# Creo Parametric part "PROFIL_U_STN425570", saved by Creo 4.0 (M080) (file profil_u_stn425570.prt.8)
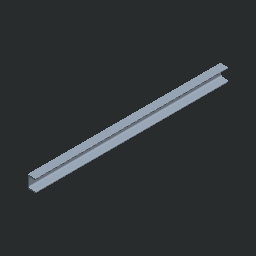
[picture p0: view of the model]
Units: millimeter Kilogram Sec (mmKs); MM, KILOGRAM, SECS
Materials in the file: OCEL_N

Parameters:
  MFG_WP_MATERIAL = "OCEL"
  NAZOV = "PROFIL_U_STN425570"
  NORMA = "STN 42 5570"
  PTC_MATERIAL_NAME = "OCEL_N"

Other parameters: HMOTNOST, HUSTOTA, D5, D1, D10

Created from: U.PRT

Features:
  1. datum plane "DTM1"
  2. datum plane "DTM2"
  3. datum plane "DTM3"

Layers: 1, 2, 3, 4, 5, 6, 7, 8, 9, 10, 11, 12, 13, 14, 15, 16, 17, 18, 19, 20, 21, 22, 23, 24, 25, 26, 27, 28, 29, 30, 31, 32

Family table entries: GENERIC, PROFIL_U_65, PROFIL_U_STN425570, value(d_val), value(i_val), PROFIL_U_80, PROFIL_U_STN425570, 2/T, 2/ , 2/-, PROFIL_U_100, PROFIL_U_STN425570, !/I, 2/Y, 2/!, 2//, PROFIL_U_120, PROFIL_U_STN425570, 2/^, 2/", 2/0, PROFIL_U_140, PROFIL_U_STN425570, !/N, 2/$, PROFIL_U_160, PROFIL_U_STN425570, 2/d, 2/%, PROFIL_U_180, PROFIL_U_STN425570, 2/ , 2/&, PROFIL_U_200, PROFIL_U_STN425570, 2/i, 2/!, 2/', PROFIL_U_240, PROFIL_U_STN425570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

Surfaces: 10 plane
